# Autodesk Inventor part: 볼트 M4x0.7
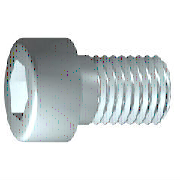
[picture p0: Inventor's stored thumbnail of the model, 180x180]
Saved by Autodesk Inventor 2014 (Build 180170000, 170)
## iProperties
IsCustomPart: 0
Created: 2015-12
Part Number: 볼트 M4x0.7
Material: 강철, 연강
Description: 6각머리 태핑 나사
Document SubType Name: Modeling
Standard: KS B 1003
Designer: mdu
Standards Organization: KS
Language: ko-KR
Size Designation: M 4 x 12
Categories: <MemberInstance><Categories><Category DisplayName="조임쇠" InternalName="e4da775c-781d-43d5-af7c-5136215cf5a6" Mnemonic="FSTN"><Category DisplayName="볼트" InternalN
Density: 7.86 g/cm^3
Mass: 2.23465 g
Surface Area: 3.30853 cm^2
Volume: 0.284306 cm^3
Appearance: 진녹색
Author: mdu
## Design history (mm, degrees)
sketch "스케치1"
  geometry: L1 (-1, 0)-(12, 0); L2 (12, 0)-(12, 2); L3 (12, 2)-(1.75, 2); L4 (1.75, 2)-(1.32, 2); L5 (1.32, 2)-(0, 2); L6 (0, 2)-(0, 3.5); L7 (0, 3.5)-(-4, 3.5); L8 (-4, 3.5)-(-4, 1.732); L9 (-4, 1.732)-(-2, 1.732); L10 (-2, 1.732)-(-1, 0); L11 (-7.2, 0)-(15.2, 0) reference; L12 (0, -0.7)-(0, 4.2) reference; L13 (1.75, 2)-(0, 2)
  constraints: 22 end point, 6 parallel, 2 collinear, 2 perpendicular, 1 horizontal, 1 point on line
  dimensions: "d1" = 10.25 distance from line of L3.end L2 (= GEL); "d2" = 0.42952 distance of L4.end L3.end (computed from GAL); "d3" = 4 distance between parallel lines of L8 L6 (= KOH); "d4" = 2 distance of L8.end L9.end (= INTI); "d5" = 60 deg angle of L10 L1; "d6" = 4 diameter of L3 L1 (= GD); "d7" = 4 diameter of L5 L1 (= BDM); "d8" = 3.4641 diameter of L9 L1 (= 1.1547 x SW); "d9" = 7 diameter of L7 L1 (= KOD); "d26" = 12 distance between parallel lines of L12 L2 (= NLG)
revolve "본체" sketch "스케치1" stored, may be unused: angle "d10" = 90 deg
sketch "스케치2"
  geometry: L1 (0, -4.9)-(0, 4.9) reference; L2 (-4.9, 0)-(4.9, 0) reference; L3 (1.732, 0)-(0.866, -1.5); L4 (0.866, -1.5)-(-0.866, -1.5); L5 (-0.866, -1.5)-(-1.732, 0); L6 (-1.732, 0)-(-0.866, 1.5); L7 (-0.866, 1.5)-(0.866, 1.5); L8 (0.866, 1.5)-(1.732, 0); 2 further points
  constraints: 12 end point, 1 coincident, 1 horizontal alignment, 1 point on line, 12 other
extrude "슬롯" join sketch "스케치2" stored distance "d11" = 10; taper "d12" = 0 deg
workplane "Work Plane1"
fillet "Fillet2" dims "d30" = 0.1 (= R)
body "Solid1"
fillet "모깎기1" dims "d17" = 0.4 (= RR)
feature "스레드" dims "d13" = 10.25 (= GEL), "d14" = 0
chamfer "모따기1" distance "d15" = 0.42941 (= -0.5 x SPD + 0.5 x GD); stored, may be unused: second distance "d16" = 0.42941 (= GUL), angle "d27" = 45 deg
other parameters: "GD" = 4 (= NND) [user parameter; used in 2 equation terms], "NLG" = 12 [user parameter; used in 1 equation term], "GEL" = 10.25 [user parameter; used in 2 equation terms], "KOD" = 7 [user parameter; used in 1 equation term], "KOH" = 4 [user parameter; used in 1 equation term], "INTI" = 2 [user parameter; used in 1 equation term], "GAL" = 0.42941 (= 0.61345 x PTC) [user parameter; used in 1 equation term], "GUL" = 0.42941 (= 0.61345 x PTC) [user parameter; used in 1 equation term], "BDM" = 4 (= NND) [user parameter; used in 1 equation term], "SW" = 3 [user parameter; used in 2 equation terms], "RR" = 0.4 [user parameter; used in 1 equation term], "SPD" = 3.14117 (= NND - 1.2269 x PTC) [user parameter; used in 1 equation term], "d19" = 0, "d28" = 0, "d29" = 0, "R" = 0.1 [user parameter; used in 1 equation term], "PHH" = 0.2 [user parameter], "GD1" = 3.14117 (= THREADDIA - 1.2269 x PTC) [user parameter], "THREADDIA" = 4 [user parameter; used in 1 equation term], "FAWI" = 45 deg [user parameter], "TPU" = 14.28571 (computed from PTC) [user parameter], "PTC" = 0.7 [user parameter; used in 5 equation terms], "NND" = 4 [user parameter; used in 3 equation terms], "TOA" = 30 deg [user parameter], "E0" = 3.465 (= 1.155 x SW) [user parameter]
